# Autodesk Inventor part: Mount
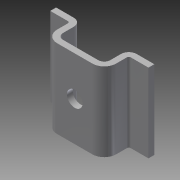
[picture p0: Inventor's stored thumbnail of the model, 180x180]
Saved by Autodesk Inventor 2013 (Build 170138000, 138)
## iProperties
Created: 2004-07
Part Number: Mount
Document SubType Name: Modeling
Designer: leeha
Manufacturer: Standard
Standards Organization: Custom
Material: Steel, Mild
Density: 7.86 g/cm^3
Mass: 511.026 g
Surface Area: 245.892 cm^2
Volume: 65.016 cm^3
Author: Autodesk, Inc.
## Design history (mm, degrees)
sketch "Sketch1"
  geometry: L1 (-48.13, 10.945)-(-30.13, 10.945); L2 (-22.13, 2.945)-(-22.13, -8.033); L3 (-16.108, -14.055)-(19.848, -14.055); L4 (25.87, -8.033)-(25.87, 2.945); L5 (33.87, 10.945)-(51.87, 10.945); L6 (-48.13, 4.945)-(-30.13, 4.945); L7 (-28.13, 2.945)-(-28.13, -8.033); L8 (-16.108, -20.055)-(19.848, -20.055); L9 (31.87, -8.033)-(31.87, 2.945); L10 (33.87, 4.945)-(51.87, 4.945); L11 (-48.13, 10.945)-(-48.13, 4.945); L12 (51.87, 4.945)-(51.87, 10.945); A1 r 8 centre (-30.13, 2.945) between (-22.13, 2.945) and (-30.13, 10.945); A2 r 8 centre (33.87, 2.945) between (33.87, 10.945) and (25.87, 2.945); A3 r 6.022 centre (-16.108, -8.033) between (-22.13, -8.033) and (-16.108, -14.055); A4 r 6.022 centre (19.848, -8.033) between (19.848, -14.055) and (25.87, -8.033); A5 r 2 centre (-30.13, 2.945) between (-28.13, 2.945) and (-30.13, 4.945); A6 r 12.022 centre (-16.108, -8.033) between (-28.13, -8.033) and (-16.108, -20.055); A7 r 12.022 centre (19.848, -8.033) between (19.848, -20.055) and (31.87, -8.033); A8 r 2 centre (33.87, 2.945) between (33.87, 4.945) and (31.87, 2.945)
  constraints: 24 end point, 16 point on circle, 8 centre point, 8 tangent, 5 collinear, 5 parallel, 3 perpendicular, 2 equal radius, 1 horizontal, 8 other
  dimensions: "d1" = 8 radius of A1; "d3" = 6 distance between parallel lines of L1 L6; "d4" = 25 distance between parallel lines of L5 L3; "d5" = 60 distance between parallel lines of L9 L7; "d6" = 100 distance between parallel lines of L12 L11
extrude "Extrusion1" new body sketch "Sketch1" distance "d7" = 80; taper "d8" = 0 deg
sketch "Sketch2"
  geometry: L1 (35.956, 80)-(0, 80) reference; L2 (35.956, 0)-(35.956, 80) reference; C1 r 8 at (17.978, 40); 2 further points
  constraints: 2 midpoint, 1 centre point, 1 horizontal alignment, 1 vertical alignment
  dimensions: "d9" = 16 diameter of C1
extrude "Extrusion2" cut sketch "Sketch2" distance "d10" = 80; taper "d11" = 0 deg
sketch "Sketch3"
  geometry: C1 r 8 at (17.978, 40) reference; C2 r 14 at (17.978, 40)
  constraints: 1 centre point, 1 coincident
  dimensions: "d12" = 28 diameter of C2
split "Split1" sketch "Sketch3"
body "Solid1"
